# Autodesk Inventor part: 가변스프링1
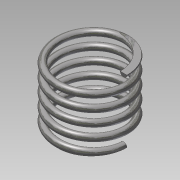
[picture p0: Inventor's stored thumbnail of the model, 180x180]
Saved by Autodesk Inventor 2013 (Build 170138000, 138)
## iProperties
Created: 2019-01
Part Number: 가변스프링1
Material: 스테인리스강
Document SubType Name: Modeling
Designer: Administrator
Density: 8.08 g/cm^3
Mass: 7.79367 g
Surface Area: 19.6283 cm^2
Volume: 0.964563 cm^3
Author: Administrator
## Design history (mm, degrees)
sketch "스케치1"
  geometry: L1 (0, 0)-(10, 0); L2 (10, 0)-(10, 18.7); L3 (10, 18.7)-(0, 18.7); L4 (0, 18.7)-(0, 0); C1 r 1 at (10, 0)
  constraints: 8 end point, 2 parallel, 1 centre point, 1 coincident, 1 horizontal, 1 perpendicular
  dimensions: "d0" = 2 diameter of C1; "d2" = 20 diameter of L2 L4; "d3" = 18.7 distance between parallel lines of L1 L3 (derived)
feature "코일1" sketch "스케치1" pitch "d4" = 10; turns "d6" = 5; dims "d5" = 18.7 (= d3), "d7" = 0, angle "d8" = 90 deg, angle "d9" = 90 deg, "d10" = 0, "d11" = 0
sketch "스케치2"
  geometry: L1 (18.7, 12.5)-(0, 12.5); L2 (0, 12.5)-(0, -12.5); L3 (0, -12.5)-(18.7, -12.5); L4 (18.7, -12.5)-(18.7, 12.5); 2 further points
  constraints: 8 end point, 2 parallel, 1 coincident, 1 horizontal, 1 midpoint, 1 perpendicular
  dimensions: "d12" = 25 distance between parallel lines of L3 L1; "d14" = 18.7 distance between parallel lines of L2 L4 (derived)
extrude "돌출1" sketch "스케치2" stored distance "d15" = 25; taper "d16" = 0 deg
node "솔리드1"
